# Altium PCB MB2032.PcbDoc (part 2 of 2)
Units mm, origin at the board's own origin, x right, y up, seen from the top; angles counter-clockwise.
Board outline 43.1 x 54.35 mm, 4 copper layers (Top Layer, Internal 1, Internal 2, Bottom Layer), stack 1.614 mm thick; 112 components, 86 nets, 372 pads, 581 vias.
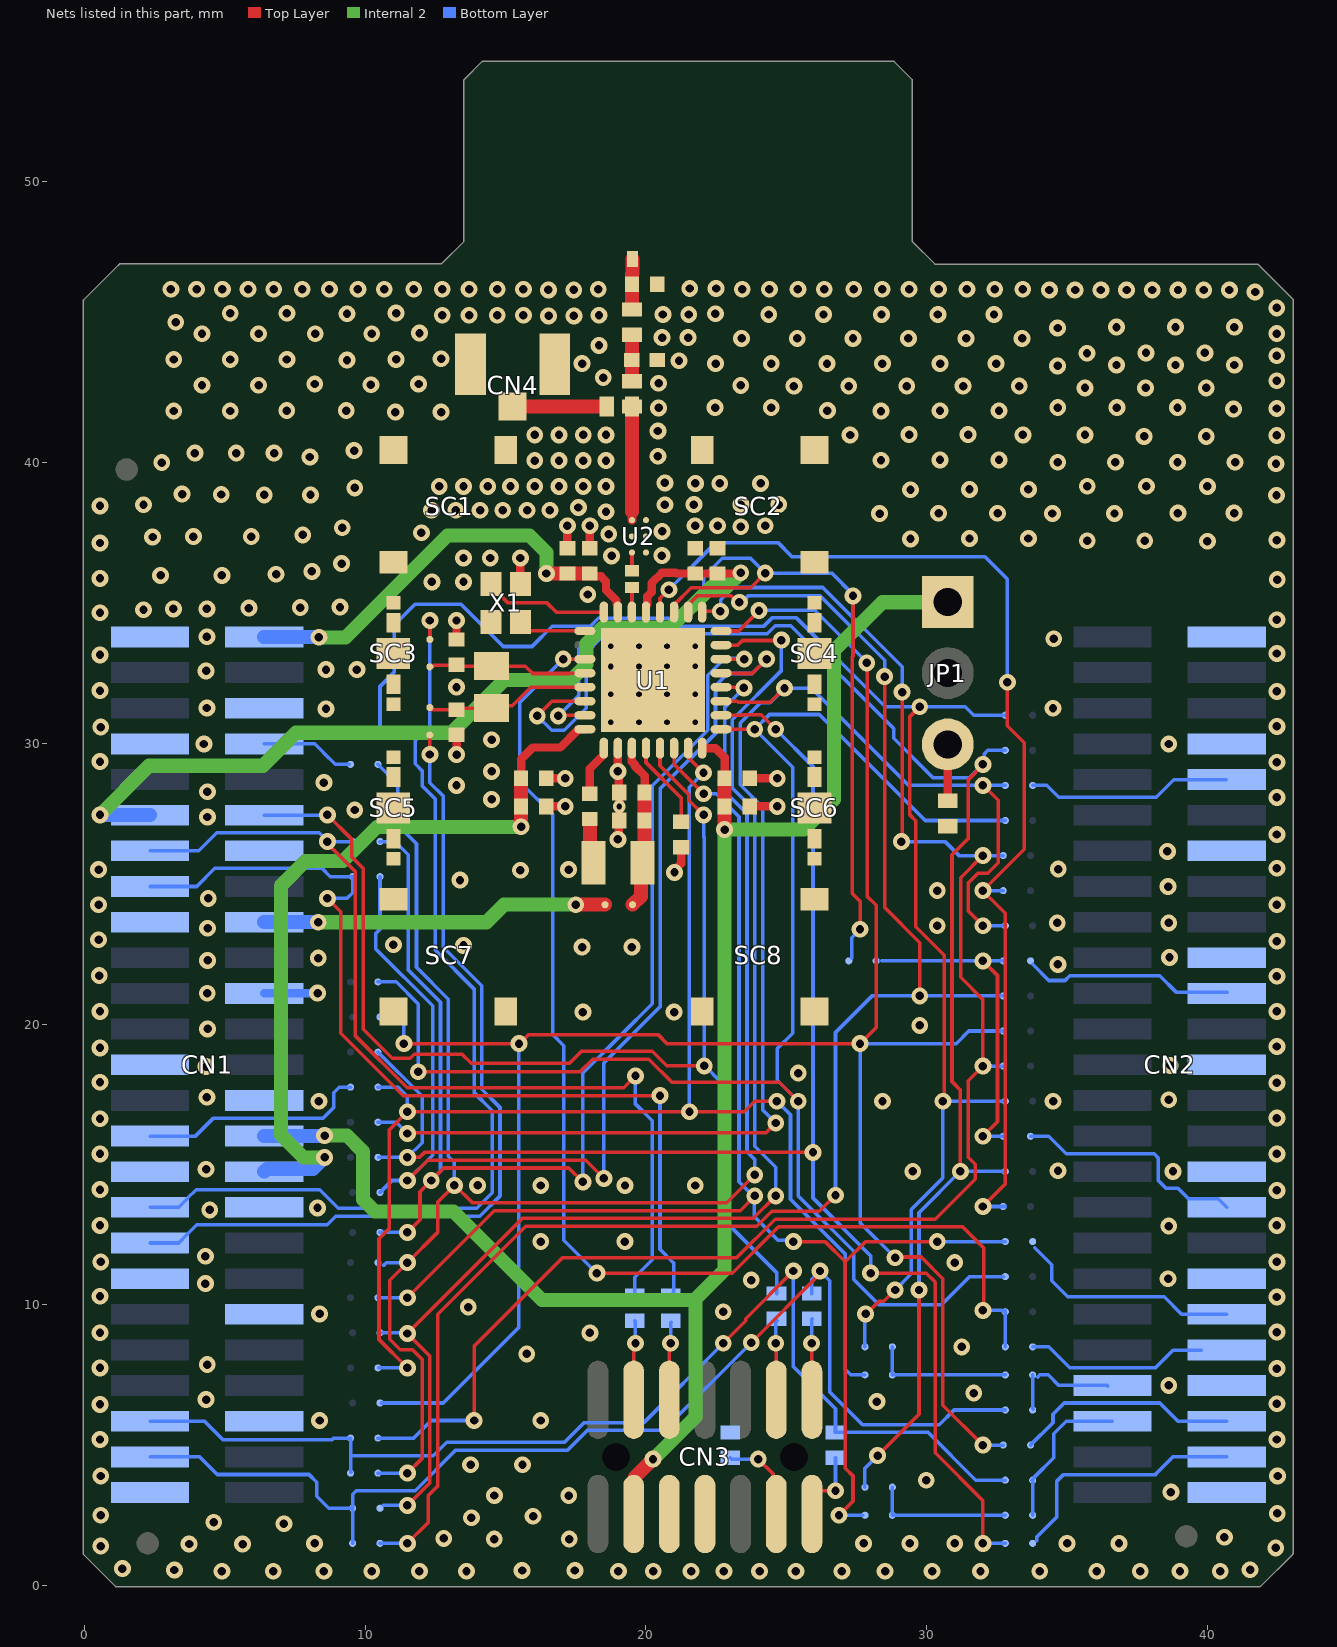
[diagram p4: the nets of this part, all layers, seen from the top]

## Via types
v1: diameter 0.6, hole 0.3, Top Layer to Bottom Layer, tented both sides, 564 vias
v2: diameter 0.45, hole 0.2, Top Layer to Bottom Layer, tented both sides, 17 vias

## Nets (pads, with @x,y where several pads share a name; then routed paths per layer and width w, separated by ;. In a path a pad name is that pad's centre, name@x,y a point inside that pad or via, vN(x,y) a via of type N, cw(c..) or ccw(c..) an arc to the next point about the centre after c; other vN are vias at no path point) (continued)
GND: C1.1 C2.1 C3.1 C4.1 C5.1 C6.1 C8.1 C9.2 C10.1 C11.1 C12.1 C13.1 C14.1 C15.1 C16.1 CN1.1 CN1.6 CN1.7 CN1.14 CN1.17 CN1.22 CN1.25 CN1.28 CN1.31 CN1.34 CN1.37 CN1.40 CN1.46 CN1.49 CN2.2 CN2.8 CN2.14 CN2.20 CN2.26 CN2.32 CN2.38 CN2.44 CN2.50 CN3.5 CN3.7 CN4.2 CN4.3 R3.1 R9.1 SC1.1 SC2.1 SC3.1 SC4.1 SC5.1 SC6.1 SC7.1 SC8.1 U1.26 U1.33 U2.A2 U2.B1 U2.B2 U2.B3 X1.2 X1.4 | length 13.1
  Top Layer w0.3: C9.2@13.25,30.3 13.251,30.299 13.251,29.597 v1(13.253,29.595) ; C8.1@13.25,33.7 v1(13.25,34.375) ; X1.2@15.525,35.925 v1(15.525,36.6) ; C14.1@16.45,27.75 v1(17.125,27.75) ; C11.1@16.45,28.75 v1(17.125,28.75) ; C3.1@17.2,36.95 v1(17.2,37.75) ; C4.1@18,36.95 v1(18,37.75) ; v1(19,26.575) 19.025,26.6 19.025,27.225 C15.1@19.05,27.25 C12.1@19.05,28.25 19.025,28.275 v1@19.025,28.925 ; v1(19,29) U1.26@19,29.825 ; v1(21.015,25.4) 21.015,25.48 21.25,25.714 C16.1@21.25,26.3 ; C13.1@23.7,27.75 v1(24.675,27.75) ; C10.1@23.7,28.75 v1(24.675,28.75)
  Bottom Layer w0.3: CN1.22@6.401,21.088 8.288,21.088 v1(8.3,21.1)
  other v1: 4.894,0.508 6.723,0.508 8.527,0.508 10.228,0.508 11.93,0.508 13.607,0.508 19.017,0.508 20.261,0.508 21.608,0.508 22.776,0.508 24.046,0.508 25.341,0.508 26.978,0.508 28.516,0.508 30.193,0.508 31.916,0.508 34.028,0.508 36.06,0.508 37.61,0.508 39.024,0.508 40.454,0.508 15.588,0.533 17.467,0.533 3.2,0.55 41.521,0.559 1.35,0.6 42.436,1.337 0.575,1.4 5.631,1.473 3.725,1.475 8.196,1.499 27.75,1.5 29.4,1.5 31,1.5 35,1.5 36.85,1.5 14.597,1.651 17.264,1.651 12.794,1.676 40.607,1.716 7.1,2.2 4.6,2.25 13.778,2.413 15.98,2.464 0.575,2.5 42.486,2.565 17.25,3.2 14.602,3.205 38.7,3.325 29.983,3.75 0.575,3.9 42.5,3.9 13.75,4.3 15.6,4.3 0.55,5.2 42.475,5.2 8.375,5.875 16.25,5.875 0.55,6.45 42.475,6.475 28.225,6.55 4.331,6.62 31.675,6.85 38.625,7.125 42.475,7.725 0.55,7.75 4.372,7.865 15.75,8.25 31.25,8.5 0.55,9 18.003,8.998 42.475,9.025 8.375,9.675 22.75,9.75 13.67,9.915 42.475,10.275 0.55,10.3 4.306,10.75 23.75,10.875 38.6,10.925 31,11.5 0.575,11.525 42.475,11.525 4.306,11.725 16.25,12.25 19.25,12.25 38.625,12.8 0.55,12.825 42.475,12.825 4.458,13.376 8.299,13.449 42.475,14.075 0.55,14.1 16.253,14.248 19.253,14.248 21.753,14.248 14,14.25 29.503,14.748 38.775,14.75 34.678,14.773 4.331,14.824 0.55,15.375 42.475,15.375 0.55,16.625 42.475,16.65 8.35,17.25 28.425,17.25 34.503,17.248 38.625,17.3 4.356,17.39 42.475,17.9 0.55,17.925 25.425,18.25 4.331,18.482 38.675,18.525 0.55,19.15 42.475,19.2 4.382,19.828 29.75,19.95 17.75,20.425 21,20.425 0.55,20.45 42.475,20.45 4.372,21.098 42.475,21.7 0.525,21.725 34.675,22.125 4.382,22.266 8.325,22.35 38.65,22.375 17.725,22.74 19.5,22.74 13.5,22.8 11,22.825 42.475,22.95 0.5,23 4.382,23.409 30.375,23.5 34.65,23.6 38.625,23.6 0.5,24.25 42.475,24.25 4.407,24.476 30.375,24.75 38.6,24.893 13.375,25.125 0.5,25.5 15.525,25.48 17.246,25.5 34.684,25.518 42.475,25.55 38.575,26.15 42.475,26.75 4.375,27.375 9.625,27.625 14.5,28 42.475,28.075 4.375,28.275 13.25,28.5 8.525,28.6 14.5,29 42.475,29.325 0.55,29.35 4.25,29.975 38.625,29.975 14.5,30.125 0.575,30.575 42.475,30.6 8.6,31.225 4.356,31.258 34.5,31.25 42.475,31.85 0.55,31.875 13.25,32 4.331,32.579 8.6,32.625 9.7,32.625 0.55,33.15 42.475,33.2 34.525,33.725 4.356,33.798 42.475,34.4 0.55,34.65 2.1,34.759 3.163,34.789 4.356,34.789 5.855,34.814 7.684,34.835 9.1,34.85 17.925,35.3 12.375,35.75 13.5,35.75 42.486,35.832 0.55,35.875 2.71,35.982 4.894,35.982 6.825,36.023 8.1,36.125 9.159,36.402 13.5,36.6 14.45,36.6 18.775,36.675 20.568,36.685 0.551,37.135 40,37.2 35.718,37.214 37.77,37.214 42.477,37.236 29.423,37.283 31.524,37.296 33.624,37.296 2.425,37.35 3.878,37.363 5.936,37.363 7.775,37.425 18.675,37.45 12,37.5 20.575,37.55 9.181,37.677 23.375,37.715 21.75,37.75 22.55,37.75 24.25,37.75 28.323,38.183 30.424,38.196 32.524,38.196 34.476,38.186 36.69,38.186 38.95,38.2 40.95,38.2 18.576,38.25 12.361,38.3 13.225,38.3 14.089,38.3 14.899,38.3 15.763,38.3 16.575,38.3 17.591,38.4 0.551,38.456 2.1,38.5 20.675,38.5 21.708,38.502 23.382,38.502 24.732,38.502 42.461,38.837 4.869,38.862 6.4,38.85 8.05,38.85 3.475,38.875 29.423,39.033 31.524,39.046 33.624,39.046 9.625,39.1 12.636,39.15 13.5,39.15 14.364,39.15 15.174,39.15 16.038,39.15 16.902,39.15 17.766,39.15 18.576,39.15 35.718,39.158 37.824,39.158 40,39.15 21.762,39.258 22.626,39.258 24.084,39.258 20.675,39.275 42.444,39.96 2.75,40 34.668,40.014 36.72,40.014 38.934,40.014 40.986,40.014 16.038,40.068 16.902,40.068 17.766,40.068 18.576,40.068 28.373,40.083 30.474,40.096 32.574,40.096 8.025,40.2 20.425,40.225 3.931,40.338 5.404,40.338 6.75,40.338 9.6,40.425 37.746,40.932 39.96,40.932 42.467,40.97 16.038,40.986 16.902,40.986 17.766,40.986 18.576,40.986 27.273,40.983 29.374,40.996 31.474,40.996 33.426,40.986 35.64,40.986 20.425,41.125 11.075,41.8 12.7,41.8 28.373,41.833 3.175,41.838 5.191,41.838 7.2,41.85 9.325,41.85 26.46,41.85 30.474,41.846 32.574,41.846 40.932,41.904 42.467,41.927 20.45,41.95 22.464,41.958 24.462,41.958 34.668,41.958 36.774,41.958 38.934,41.958 35.64,42.66 37.8,42.66 39.96,42.66 25.27,42.725 27.223,42.725 29.29,42.725 31.298,42.725 33.298,42.725 4.183,42.755 6.2,42.755 23.373,42.75 10.2,42.775 8.2,42.8 11.9,42.8 20.45,42.825 42.467,42.918 18.475,43.025 34.661,43.444 36.762,43.476 38.862,43.476 40.962,43.476 17.725,43.525 22.48,43.525 24.461,43.525 26.448,43.525 28.423,43.525 30.48,43.525 32.473,43.525 21.175,43.625 9.35,43.65 3.175,43.671 5.191,43.671 7.208,43.671 11.1,43.675 12.7,43.7 42.467,43.807 35.711,43.897 37.812,43.909 39.912,43.909 18.325,44.175 23.405,44.425 25.386,44.425 27.373,44.425 29.348,44.425 31.405,44.425 33.398,44.425 20.575,44.45 21.5,44.45 4.183,44.588 6.2,44.588 8.216,44.588 10.232,44.588 42.467,44.594 11.932,44.613 34.661,44.794 36.762,44.826 38.862,44.826 40.962,44.826 3.25,45 16.531,45.224 17.431,45.224 12.742,45.25 13.7,45.25 14.7,45.25 15.631,45.25 18.325,45.249 20.6,45.275 21.525,45.275 24.37,45.275 26.323,45.275 28.39,45.275 30.398,45.275 32.398,45.275 9.35,45.3 22.473,45.3 5.191,45.321 7.208,45.321 11.1,45.325 42.467,45.509 41.699,46.077 16.525,46.15 17.425,46.15 34.372,46.147 35.288,46.147 36.204,46.147 37.12,46.147 38.036,46.147 38.952,46.147 39.868,46.147 40.784,46.147 3.077,46.177 3.992,46.177 4.908,46.177 5.824,46.177 6.74,46.177 7.757,46.175 8.722,46.175 9.738,46.175 10.675,46.175 11.725,46.175 12.742,46.175 13.7,46.175 14.7,46.175 15.631,46.175 18.3,46.175 23.43,46.175 24.395,46.175 25.411,46.175 26.348,46.175 27.398,46.175 28.415,46.175 29.373,46.175 30.423,46.175 31.43,46.175 32.423,46.175 33.423,46.175 21.561,46.2 22.498,46.2
  other v2: 19.05,27.75 18.75,30.75 19.75,30.75 20.75,30.75 21.75,30.75 18.75,31.75 19.75,31.75 20.75,31.75 21.75,31.75 18.75,32.737 19.75,32.737 20.75,32.75 21.75,32.75 18.75,33.457 19.75,33.457 20.75,33.457 21.75,33.457
LD1: CN2.10 SB9.2 | length 7.3
  Bottom Layer w0.127: SB9.2@33.775,28.5 34.275,28.5 34.7,28.075 38.175,28.075 38.8,28.7 CN2.10@40.675,28.7
LD2: CN1.29 SB16.2 | length 8.2
  Bottom Layer w0.127: CN1.29@2.334,16.008 3.953,16.008 4.595,16.65 8.5,16.65 8.875,17.025 8.875,17.55 9.075,17.75 SB16.2@9.475,17.75
LD3: CN2.48 SB7.2 | length 8.8
  Bottom Layer w0.127: 33.925,1.6 33.925,1.725 34.625,2.425 34.625,3.7 34.875,3.95 38.15,3.95 ; 38.138,3.953 38.764,4.578 CN2.48@40.688,4.578
LPUART_CTS: SB49.1 SB52.2 SB53.2 | length 11.7
  Top Layer w0.127: v1(32,16) 32.523,16.523 32.523,21.727 v1(32,22.25)
  Bottom Layer w0.127: 28.4,22.25 v1(32,22.25) SB52.2@32.7,22.25 ; v1(32,16) SB53.2@32.725,16 SB53.2@32.75,16
LPUART_RTS: CN1.8 SB45.2 | length 3.3
  Bottom Layer w0.127: CN1.8@6.401,29.978 8.203,29.978 8.5,29.682 8.5,29.675 8.925,29.25 SB45.2@9.425,29.25
LPUART_RX: SB31.2 SB35.2 SB57.1 | length 5
  Bottom Layer w0.127: SB31.2@28.775,2.5 SB57.1@32.8,2.5 ; SB35.2@28.775,3.5 28.775,2.55 SB31.2@28.8,2.525
LPUART_TX: SB29.2 SB33.2 SB55.1 | length 5
  Bottom Layer w0.127: SB29.2@28.775,7.5 SB33.2@28.775,8.5 ; SB29.2@28.8,7.525 28.825,7.5 SB55.1@32.8,7.5
NetANT1_1: ANT1.1 C1.2 R10.2 | length 1.7
  Top Layer w0.5: R10.2@19.5,45.5 C1.2@19.5,46.35 ; C1.2@19.5,46.425 19.5,46.725 19.52,46.745 ANT1.1@19.52,47.25
NetC2_2: C2.2 R1.2 R10.1 | length 1.6
  Top Layer w0.5: R1.2@19.5,42.9 R10.1@19.5,44.525
NetC7_1: C7.1 U1.14 | length 0.9
  Top Layer w0.15: U1.14@19.5,34.675 C7.1@19.5,35.55
NetC7_2: C7.2 U2.A3 | length 0.6
  Top Layer w0.15: C7.2@19.5,36.15 U2.A3@19.5,36.795
NetC8_2: C8.2 SB1.2 U1.20 X2.2 | length 5.6
  Top Layer w0.127: SB1.2@12.301,32.749 12.412,32.749 12.438,32.775 13.225,32.775 C8.2@13.25,32.8 ; C8.2@13.3,32.775 13.325,32.75 X2.2@14.5,32.75 15.7,32.75 15.963,32.487 17.263,32.487 17.276,32.5 U1.20@17.825,32.5
NetC9_1: C9.1 SB2.2 U1.21 X2.1 | length 5.7
  Top Layer w0.127: SB2.2@12.301,31.201 12.414,31.201 ; 12.415,31.2 C9.1@13.25,31.2 ; C9.1@13.325,31.25 X2.1@14.5,31.25 14.591,31.341 15.241,31.341 15.9,32 U1.21@17.8,32
NetC12_2: C12.2 C15.2 L3.1 SB3.1 U1.27 | length 5.9
  Top Layer w0.3: U1.27@19.5,29.825 19.5,29.349 19.6,29.249 19.6,29.2 19.95,28.85 C12.2@19.95,28.3
  Top Layer w0.5: SB3.1@19.525,24.25 19.82,24.545 19.82,25.695 L3.1@19.875,25.75 ; L3.1@19.875,25.775 19.95,25.85 C15.2@19.95,27.25 C12.2@19.95,28.25
NetC16_2: C16.2 U1.28 | length 3.1
  Top Layer w0.127: U1.28@20,29.825 20,29.314 21.25,28.064 C16.2@21.25,27.2
NetCN2_22: CN2.22 SB52.1 | length 7.5
  Bottom Layer w0.127: 33.775,22.125 34.35,21.55 34.925,21.55 35.1,21.725 38.3,21.725 38.9,21.125 CN2.22@40.7,21.125
NetCN2_34: CN2.34 SB53.1 | length 8.5
  Bottom Layer w0.127: SB53.1@33.7,16 34.35,16 34.975,15.375 38.1,15.375 38.25,15.225 38.25,14.425 38.525,14.15 38.95,14.15 39.325,13.775 40.385,13.775 CN2.34@40.691,13.468
NetCN2_43: CN2.43 SB54.2 SB55.2 | length 3.9
  Bottom Layer w0.127: SB55.2@33.775,7.5 33.775,6.3 SB54.2@33.8,6.275 ; 33.95,7.425 34.025,7.5 34.325,7.5 34.7,7.125 36.425,7.125 CN2.43@36.45,7.1
NetCN2_45: CN2.45 SB56.2 SB57.2 | length 5.5
  Bottom Layer w0.127: SB56.2@33.75,3.75 33.775,3.725 SB57.2@33.775,2.5 ; SB56.2@33.775,3.75 33.775,3.784 33.838,3.848 33.838,3.864 34.525,4.55 34.525,5.4 34.975,5.85 CN2.45@36.6,5.85
NetCN3_4: CN3.4 R7.1 | length 2.8
  Top Layer w0.127: CN3.4@19.561,6.614 19.561,8.561 v1(19.625,8.625)
  Bottom Layer w0.127: R7.1@19.6,9.425 19.625,9.4 v1(19.625,8.625)
NetCN3_6: CN3.6 R6.1 | length 2.8
  Top Layer w0.127: CN3.6@20.831,6.614 20.831,8.581 v1(20.875,8.625)
  Bottom Layer w0.127: v1(20.875,8.625) 20.875,9.35 R6.1@20.9,9.375
NetCN3_11: CN3.11 R9.2 | length 3.2
  Top Layer w0.127: v1(24,4.5) 24.524,3.976 24.524,2.662 CN3.11@24.641,2.544
  Bottom Layer w0.127: R9.2@23,4.55 23.05,4.5 v1(24,4.5)
NetCN3_12: CN3.12 R5.1 | length 2.8
  Top Layer w0.127: v1(24.625,8.625) 24.641,8.609 CN3.12@24.641,6.614
  Bottom Layer w0.127: v1(24.625,8.625) 24.625,9.375 R5.1@24.675,9.425
NetCN3_13: CN3.13 R8.2 | length 2.7
  Top Layer w0.127: CN3.13@25.911,2.544 25.911,3.092 26.195,3.375 v1(26.75,3.375)
  Bottom Layer w0.127: v1(26.75,3.375) R8.2@26.75,4.55
NetCN3_14: CN3.14 R4.1 | length 2.9
  Top Layer w0.127: v1(25.9,8.625) 25.911,8.614 CN3.14@25.911,6.614
  Bottom Layer w0.127: v1(25.9,8.625) 25.9,9.475 R4.1@25.925,9.5
NetCN4_1: CN4.1 R2.2 | length 3.4
  Top Layer w0.5: CN4.1@15.25,42 R2.2@18.6,42
NetJP1_3: JP1.3 R3.2 | length 2
  Top Layer w0.3: R3.2@30.75,27.95 JP1.3@30.75,29.96 JP1.3@30.75,29.975
NetL2_1: L2.1 L3.2 | length 1.6
  Top Layer w0.5: L2.1@18,27.3 18,25.925 L3.2@18.125,25.8
NetL2_2: L2.2 U1.25 | length 1.8
  Top Layer w0.3: L2.2@18,28.225 18,29.1 18.5,29.6 U1.25@18.5,29.825
NetR1_1: R1.1 R2.1 U2.A1 | length 4.1
  Top Layer w0.32: U2.A1@19.5,37.949 19.5,38.25
  Top Layer w0.5: 19.5,38.25 R2.1@19.5,42
NetU1_16: U1.16 X1.3 | length 4.2
  Top Layer w0.127: X1.3@14.65,35.45 14.787,35.314 14.787,35.299 15.086,35 16.475,35 16.8,34.675 U1.16@18.475,34.675
NetU1_17: U1.17 X1.1 | length 2.4
  Top Layer w0.127: X1.1@15.525,34.325 15.837,34.013 17.812,34.013 U1.17@17.825,34
OSC32_IN: CN1.33 SB1.1 | length 35.4
  Top Layer w0.127: SB1.1@12.3,33.7 v1(12.3,34.375)
  Bottom Layer w0.127: CN1.33@2.334,13.468 3.356,13.468 3.663,13.775 3.663,13.788 3.975,14.1 8.375,14.1 9.039,13.437 13.97,13.437 14.523,13.99 14.523,16.91 13.875,17.558 13.875,21.25 12.5,22.625 12.5,28.008 12.023,28.485 12.023,29.027 11.775,29.275 11.775,30.1 12.3,30.625 v1(12.3,34.375)
OSC32_OUT: CN1.35 SB2.1 | length 30.6
  Top Layer w0.127: v1(12.3,29.6) SB2.1@12.3,30.3
  Bottom Layer w0.127: CN1.35@2.334,12.198 3.356,12.198 3.663,12.505 3.663,12.513 4,12.85 8.65,12.85 8.95,13.15 14.075,13.15 14.8,13.875 14.8,17.025 14.152,17.673 14.152,21.365 12.777,22.74 12.777,28.123 12.3,28.6 v1(12.3,29.6)
PA0: SB4.2 SB6.2 SB12.2 SB23.2 U1.8 | length 77.2
  Top Layer w0.127: v1(11.375,19.3) 15.5,19.3 15.825,19.625 20.425,19.625 20.748,19.302 21.34,19.302 21.342,19.3 v1(27.625,19.3) 28.2,19.875 28.2,24.225 27.875,24.55 27.875,32.857 v1(27.866,32.866) ; U1.8@22.675,34 23.3,34 v1(24.024,34.726) ; v1(28.875,11.675) 28.9,11.7 29.8,11.7 30.577,10.923 30.577,6.423 v1(32,5)
  Bottom Layer w0.127: SB4.2@10.526,20.274 SB4.2@10.639,20.274 ; SB23.2@10.575,6.5 12.775,6.5 15.475,9.2 v1(15.475,19.3) ; SB4.2@10.64,20.275 11.075,20.275 11.375,19.975 v1(11.375,19.3) ; v1(24.024,34.726) 24.041,34.742 26.007,34.742 27.866,32.884 v1(27.866,32.866) ; v1(28.875,11.675) 27.625,12.925 v1(27.625,19.3) 31.05,19.3 31.5,19.75 SB12.2@32.725,19.75 ; v1(32,5) SB6.2@32.725,5
PA1: SB25.2 SB38.2 U1.7 | length 47.2
  Top Layer w0.127: v1(11.5,2.85) 12.298,3.648 12.298,4.465 12.3,4.467 12.3,8.175 v1(11.5,8.975) 15.6,13.075 23.825,13.075 v1(24.625,13.875) ; U1.7@22.675,33.5 23.274,33.5 23.435,33.661 24.811,33.661 v1(24.825,33.675)
  Bottom Layer w0.127: SB25.2@10.525,9 11.475,9 v1(11.5,8.975) ; 10.65,2.85 v1(11.5,2.85) ; v1(24.625,13.875) 24.625,14.9 23.875,15.65 23.875,27.608 23.075,28.408 23.075,30.835 24.812,32.573 24.812,32.887 24.813,32.888 24.813,33.663 v1(24.825,33.675)
PA2: SB11.2 SB19.2 U1.6 | length 44.6
  Top Layer w0.127: v1(11.5,12.575) 11.95,13.025 11.95,14.025 12.796,14.871 17.254,14.871 v1(17.75,14.375) ; U1.6@22.675,33 v1(23.5,33)
  Bottom Layer w0.127: SB19.2@10.525,12.575 v1(11.5,12.575) ; SB11.2@10.525,26.5 11.05,26.5 11.525,26.025 11.525,21.925 12.679,20.771 12.679,14.754 v1(12.35,14.425) ; v1(17.75,14.375) 17.75,18.25 19.125,19.625 20.225,20.725 20.225,28.492 22.198,30.465 22.198,32.423 22.8,33.025 23.2,33.025 ; 23.2,33 v1(23.5,33)
PA3: SB17.2 SB30.2 U1.5 | length 44.1
  Top Layer w0.127: v1(11.5,14.425) 12.223,15.148 17.852,15.148 v1(18.5,14.5) ; U1.5@22.675,32.5 23.274,32.5 23.287,32.487 23.787,32.487 24.299,32.999 v1(24.299,33)
  Bottom Layer w0.127: SB30.2@10.525,14 10.95,14.425 v1(11.5,14.425) 12.4,15.325 12.4,15.808 12.402,15.81 12.402,20.225 ; SB17.2@10.525,25.25 10.525,23.375 10.375,23.225 10.375,22.675 12.4,20.65 12.4,20.225 ; v1(18.5,14.5) 18.5,18.608 20.502,20.61 20.502,28.377 22.475,30.35 22.475,32.05 22.912,32.487 23.787,32.487 24.299,32.999 v1(24.299,33)
PA8: SB39.2 SB41.2 SB51.1 U1.9 | length 58.8
  Top Layer w0.127: v1(13.875,5.875) 13.875,8.525 17.025,11.675 23.225,11.675 24.6,13.05 30.3,13.05 31.725,14.475 31.725,15 31.475,15.25 31.475,17.975 v1(32,18.5) 32,20.875 31.21,21.665 31.21,25.209 v1(32,26) ; U1.9@22,34.675 22.025,34.7 v1(22.65,34.7) ; v1(29.1,26.5) 29.125,26.525 v1(29.125,31.825)
  Bottom Layer w0.127: SB51.1@10.45,5.25 11.725,5.25 12.35,5.875 v1(13.875,5.875) ; v1(22.65,34.7) 22.666,34.716 22.666,35.116 23.1,35.55 26.3,35.55 29.125,32.725 v1(29.125,31.825) ; v1(29.1,26.5) 30.65,26.5 31.15,26 v1(32,26) SB41.2@32.725,26 ; v1(32,18.5) SB39.2@32.725,18.5
PA9: SB46.2 SB47.2 U1.10 | length 58.8
  Top Layer w0.127: v1(11.5,1.5) 12.25,2.25 12.25,3.208 12.575,3.533 12.575,4.35 12.577,4.352 12.577,9.66 15.715,12.798 23.948,12.798 24.45,13.3 24.458,13.3 24.485,13.327 26.177,13.327 v1(26.75,13.9) ; U1.10@21.5,34.675 21.5,34.925 21.839,35.264 23.015,35.264 23.253,35.026 v1(23.326,35.026) ; v1(28.5,32.375) 28.5,24.15 29.75,22.9 v1(29.75,21)
  Bottom Layer w0.127: SB46.2@10.525,1.5 v1(11.5,1.5) ; v1(23.326,35.026) 23.412,35.026 23.637,35.25 26.208,35.25 28.5,32.958 v1(28.5,32.375) ; v1(26.75,13.9) 26.75,19.7 28.05,21 v1(29.75,21) SB47.2@32.725,21
PA10: SB48.2 SB49.2 U1.11 | length 40.5
  Top Layer w0.127: U1.11@21,34.675 21,34.925 21.615,35.541 23.727,35.541 v1(24.25,36.063) ; v1(27.375,35.25) 27.375,33.101 27.348,33.074 27.348,24.652 27.625,24.375 v1@27.625,23.425
  Bottom Layer w0.127: SB48.2@10.525,30.5 10.525,32.025 11.025,32.525 11.025,34.2 11.773,34.948 13.41,34.948 14.91,33.448 15.94,33.448 16.665,34.173 18.023,34.173 18.304,34.454 21.271,34.454 22.05,35.233 22.05,35.921 22.717,36.588 23.725,36.588 v1(24.25,36.063) 26.612,36.063 27.375,35.3 v1(27.375,35.25) ; 27.325,22.35 27.325,23.075 v1(27.625,23.375)
PA11: SB43.2 SB44.2 U1.12 | length 39.6
  Top Layer w0.127: U1.12@20.5,34.675 20.5,35.172 20.799,35.471 v1(20.816,35.471) ; v1(32,13.5) 32.8,14.3 32.8,23.95 v1(32,24.75) 33.475,26.225 33.475,30.025 32.875,30.625 v1(32.875,32.175)
  Bottom Layer w0.127: v1(20.816,35.471) 22.495,37.15 24.7,37.15 25.198,36.652 26.14,36.652 26.142,36.65 32.075,36.65 32.875,35.85 v1(32.875,32.175) ; v1(32,13.5) SB44.2@32.725,13.5 SB44.2@32.8,13.5 ; v1(32,24.75) SB43.2@32.725,24.75
PB0: SB8.1 SB28.1 SB45.1 U1.4 | length 60.5
  Top Layer w0.127: v1(11.5,4) 12.023,4.523 12.023,8.06 11.683,8.4 11.25,8.4 10.875,8.775 10.875,10.875 v1(11.5,11.5) 12.575,12.575 12.575,13.65 v1(13.175,14.25) ; v1@13.175,14.275 13.825,13.625 15.367,13.625 15.371,13.629 22.879,13.629 v1(23.875,14.625) ; U1.4@22.675,32 23.46,32 v1(23.487,31.973)
  Bottom Layer w0.127: SB28.1@10.45,4 v1(11.5,4) ; SB45.1@10.45,29.25 11.15,28.55 11.15,27.1 11.825,26.425 11.825,22.017 12.956,20.886 12.956,15.294 13.175,15.075 v1(13.175,14.25) ; 10.65,11.4 10.75,11.5 v1(11.5,11.5) ; v1(23.487,31.973) 23.487,31.96 22.798,31.271 22.798,28.294 23.598,27.494 23.598,15.452 23.875,15.175 v1(23.875,14.625)
PB1: SB9.1 SB10.1 SB22.1 U1.3 | length 50
  Top Layer w0.127: v1(11.5,16.1) 11.525,16.125 24.275,16.125 v1(24.625,16.475) ; U1.3@22.675,31.5 23.247,31.5 23.287,31.46 24.425,31.46 v1(24.933,31.967) ; v1@31.975,23.525 31.487,24.014 31.487,25.037 31.825,25.375 32.175,25.375 32.55,25.75 32.55,27.975 v1@32,28.525
  Bottom Layer w0.127: SB10.1@10.45,16.5 11.1,16.5 v1(11.5,16.1) ; v1(24.625,16.475) 24.152,16.948 24.152,27.723 23.352,28.523 23.352,30.721 24.081,31.45 24.416,31.45 v1(24.933,31.967) 25.883,31.967 29.35,28.5 v1(32,28.5) SB9.1@32.8,28.5 ; v1(32,23.5) 32.75,23.5 SB22.1@32.775,23.525
PB2: SB5.1 SB7.1 SB13.1 U1.2 | length 56.4
  Top Layer w0.127: v1(11.5,15.25) 11.933,15.25 12.108,15.425 v1(25.95,15.425) ; U1.2@22.675,31 23.424,31 23.437,31.013 24.112,31.013 v1(24.625,30.5) ; v1(28,11.125) 29.983,11.125 30.3,10.808 30.3,4.725 32,3.025 v1(32,1.5)
  Bottom Layer w0.127: SB13.1@10.45,19 12.025,17.425 12.025,15.775 v1(11.5,15.25) SB5.1@10.475,15.25 ; v1(24.625,30.5) 25.95,29.175 25.95,13.8 28,11.75 v1(28,11.125) ; v1(32,1.5) SB7.1@32.8,1.5
PB3: SB14.1 SB15.1 SB24.1 U1.1 | length 58.1
  Top Layer w0.127: v1(11.889,18.3) 17.65,18.3 18.098,18.748 20.102,18.748 20.925,17.925 24.75,17.925 v1(25.425,17.25) ; U1.1@22.675,30.5 v1(23.875,30.5)
  Bottom Layer w0.127: SB15.1@10.45,21.5 11.1,21.5 11.889,20.712 v1(11.889,18.3) ; SB24.1@32.75,11 31.525,11 30.525,10 28.3,10 27.4,10.9 27.4,11.9 25.425,13.875 v1(25.425,17.25) 24.675,18 24.675,19.125 25.225,19.675 25.225,29.15 v1(23.875,30.5) 24.4,31.025 26.175,31.025 29.95,27.25 SB14.1@32.8,27.25
PB4: SB16.1 SB18.1 SB29.1 U1.31 | length 50.8
  Top Layer w0.127: v1(11.5,7.75) 10.49,8.76 10.49,12.354 10.85,12.715 10.85,16.225 v1(11.5,16.875) v1(21.55,16.875) 23.5,16.875 23.875,17.25 v1(24.665,17.25) ; U1.31@21.5,29.825 21.533,29.792 21.533,29.467 v1(22.05,28.95)
  Bottom Layer w0.127: SB16.1@10.45,17.75 11.175,17.75 11.5,17.425 v1(11.5,16.875) ; SB18.1@10.475,7.75 v1(11.5,7.75) ; v1(21.55,16.875) 21.538,16.887 21.538,28.439 v1(22.05,28.95) ; v1(24.665,17.25) 25.148,16.767 25.148,13.76 27.102,11.806 27.102,7.698 27.3,7.5 SB29.1@27.8,7.5
PB5: SB20.1 SB21.1 SB31.1 U1.30 | length 53.2
  Top Layer w0.127: v1(11.5,10.25) 14.598,13.348 15.481,13.348 15.485,13.352 23.352,13.352 v1(23.875,13.875) ; U1.30@21,29.825 21,29.25 22.05,28.2 v1(22.052,28.2) ; v1(25.25,12.25) 26.375,12.25 27.1,11.525 ; v1(26.875,2.5) 27.375,3 27.375,3.9 27.1,4.175 27.1,11.525 ; v1(30.375,12.25) 27.825,12.25 27.1,11.525
  Bottom Layer w0.127: SB21.1@10.45,10.25 v1(11.5,10.25) ; v1(22.052,28.2) 22.5,28.2 23.313,27.386 23.313,14.387 23.85,13.85 23.85,13.15 24.7,12.3 25.2,12.3 v1(25.25,12.25) ; v1(26.875,2.5) SB31.1@27.725,2.5 ; v1(30.375,12.25) SB20.1@32.8,12.25
PB6: SB32.1 SB33.1 SB40.1 U1.23 | length 47.7
  Top Layer w0.127: v1(16.875,30.975) 16.9,31 U1.23@17.825,31 ; v1@27.85,9.675 28.3,10.125 28.475,10.125 v1(28.875,10.525) ; v1(29.75,31.3) 29.402,30.952 29.402,27.448 29.613,27.237 29.613,23.462 30.623,22.452 30.623,17.298 v1(30.575,17.25)
  Bottom Layer w0.127: v1(16.875,30.975) 17.6,31.7 17.6,33.35 18.427,34.177 24.202,34.177 24.49,34.465 25.36,34.465 28.525,31.3 v1(29.75,31.3) 31.375,31.3 31.675,31 SB32.1@32.8,31 ; SB33.1@27.8,8.5 27.8,9.65 v1(27.825,9.675) ; v1(28.875,10.525) 29.448,11.098 29.448,13.39 30.575,14.517 v1(30.575,17.25) SB40.1@32.8,17.25
PB7: SB34.1 SB35.1 SB42.1 U1.22 | length 53.9
  Top Layer w0.127: v1(16.125,30.975) 16.65,31.5 U1.22@17.825,31.5 ; v1(28.25,4.625) 29.725,6.1 v1(29.725,10.525) ; v1(31.2,14.75) 31.198,14.752 31.198,17.652 30.9,17.95 30.9,26.025 31.487,26.612 31.487,28.713 32,29.226 v1(32,29.25)
  Bottom Layer w0.127: v1(16.125,30.975) 16.638,30.462 17.088,30.462 17.877,31.251 17.877,33.235 18.542,33.9 24.317,33.9 24.605,34.188 25.162,34.188 28.825,30.525 28.825,30.175 30.223,28.777 31.527,28.777 v1(32,29.25) 32.057,29.307 32.057,29.632 32.175,29.75 SB34.1@32.8,29.75 ; SB35.1@27.8,3.5 27.8,4.175 v1(28.25,4.625) v1@28.275,4.65 ; v1(29.725,10.525) 29.725,13.275 v1(31.2,14.75) SB42.1@32.8,14.75
PB14: SB36.1 SB37.1 U1.19 | length 43.6
  Top Layer w0.127: v1(17.05,33) U1.19@17.825,33 ; v1(18.25,11.125) 23.075,11.125 24.723,12.773 31.277,12.773 32.025,12.025 v1@32.025,9.8
  Bottom Layer w0.127: v1(17.05,33) 15.502,31.452 15.502,28.636 16.675,27.463 16.675,19.625 17.075,19.225 17.075,12.3 v1(18.25,11.125) ; v1(32,9.8) 32.662,9.8 32.688,9.774 32.774,9.774 SB36.1@32.788,9.788 ; SB36.1@32.775,9.8 SB36.1@32.787,9.788 ; SB37.1@32.8,8.5 SB36.1@32.8,9.75 32.8,9.775 SB36.1@32.788,9.788 ; SB36.1@32.8,9.8 SB36.1@32.788,9.788
T_NRST: CN1.12 R5.2 U1.29 | length 44.7
  Top Layer w0.127: v1(8.65,27.45) 9.525,26.575 9.525,25.942 9.927,25.54 9.927,19.815 10.967,18.775 11.6,18.775 11.75,18.925 13.448,18.925 13.775,18.598 17.275,18.598 17.702,19.025 20.225,19.025 20.74,18.51 v1(22.075,18.51) ; U1.29@20.5,29.825 20.5,29.206 21.527,28.179 21.527,27.973 22.05,27.45 v1(22.052,27.45)
  Bottom Layer w0.127: CN1.12@6.401,27.438 8.638,27.438 v1(8.65,27.45) ; v1(22.052,27.45) 22.05,27.448 22.05,26.675 22.075,26.65 22.075,18.525 22.675,17.925 22.675,13.125 24.651,11.149 R5.2@24.651,10.397
T_SWCLK: CN1.15 R6.2 SB17.1 | length 33.8
  Top Layer w0.127: v1(8.65,24.475) 9.125,24 9.125,19.675 11.35,17.45 v1(20.5,17.45)
  Bottom Layer w0.127: CN1.15@2.334,24.898 3.991,24.898 4.636,25.543 8.457,25.543 8.75,25.25 SB17.1@9.55,25.25 ; v1(8.65,24.475) 9.35,24.475 9.55,24.675 SB17.1@9.55,25.25 ; SB17.1@9.575,25.25 SB17.1@9.55,25.25 ; v1(20.5,17.45) 20.5,11.975 20.975,11.5 ; R6.2@20.887,10.328 20.982,10.423 20.982,11.5
T_SWDIO: CN1.13 R7.2 SB11.1 | length 34
  Top Layer w0.127: v1@8.625,26.45 9.65,25.425 9.65,19.575 11.498,17.727 19.202,17.727 v1(19.625,18.15)
  Bottom Layer w0.127: CN1.13@2.334,26.168 4.067,26.168 4.712,26.813 8.362,26.813 v1@8.675,26.5 ; v1(8.65,26.5) v1@8.675,26.5 ; SB11.1@9.475,26.5 v1@8.675,26.5 ; R7.2@19.6,10.45 19.6,10.975 20.225,11.6 20.225,11.858 20.223,11.86 20.223,16.552 19.625,17.15 v1(19.625,18.15)
T_VCP_RX: CN1.45 R8.1 SB28.2 SB51.2 SB56.1 | length 40.3
  Top Layer w0.127: v1(22.75,8.625) 23.55,9.425 23.55,9.5 v1(25.25,11.2)
  Bottom Layer w0.127: CN1.45@2.334,5.848 4.274,5.848 4.925,5.198 8.823,5.198 8.875,5.25 SB51.2@9.475,5.25 9.475,4.625 ; SB28.2@9.5,4.025 9.475,4.05 9.475,4.625 ; v1(22.75,8.625) 19.927,5.802 17.802,5.802 17.1,5.1 12.9,5.1 12.425,4.625 9.475,4.625 ; v1(25.25,11.2) 25.25,7.8 26.75,6.3 R8.1@26.75,5.5 ; R8.1@26.725,5.475 26.749,5.45 30.05,5.45 31.75,3.75 SB56.1@32.8,3.75
T_VCP_TX: CN1.47 R4.2 SB38.1 SB46.1 SB54.1 | length 42.3
  Top Layer w0.127: v1(23.75,8.65) 26.2,11.1 v1(26.2,11.2)
  Bottom Layer w0.127: CN1.47@2.334,4.578 4.102,4.578 4.728,3.953 7.997,3.953 8.275,3.675 8.275,3.175 8.7,2.75 SB38.1@9.55,2.75 9.55,3.25 9.675,3.375 11.775,3.375 13.223,4.823 17.215,4.823 17.917,5.525 20.625,5.525 v1(23.75,8.65) ; SB46.1@9.55,1.5 SB38.1@9.55,2.725 ; R4.2@25.909,10.397 25.909,10.902 26.175,11.168 v1@26.175,11.225 ; v1(26.2,11.2) 26.55,10.85 26.55,6.892 27.715,5.727 30.452,5.727 30.975,6.25 SB54.1@32.8,6.25
USER1: CN2.46 SB6.1 | length 8.1
  Bottom Layer w0.127: SB6.1@33.7,5 34.5,5.8 34.5,6.1 34.9,6.5 38.3,6.5 38.952,5.848 CN2.46@40.691,5.848
USER2: CN2.40 SB20.2 | length 8.2
  Bottom Layer w0.127: 33.85,12.025 34.45,11.425 34.45,10.85 35.022,10.278 38.46,10.278 39.08,9.658 CN2.40@40.688,9.658
USER3: CN2.42 SB37.2 | length 6.6
  Bottom Layer w0.127: SB37.2@33.775,8.5 34.35,8.5 35.1,7.75 38.15,7.75 38.775,8.375 CN2.42@39.775,8.375
VDD1: C3.2 C4.2 CN1.2 U1.15 | length 16
  Top Layer w0.3: C4.2@18,36.05 18.105,35.945 18.399,35.945 18.575,35.769 18.575,35.461 18.95,35.086 18.95,34.95 19,34.9 U1.15@19,34.675
  Top Layer w0.5: v1(16.45,36.05) C3.2@17.2,36.05 C4.2@18,36.05
  Internal 2 w0.5: v1@8.375,33.775 9.3,33.775 12.925,37.4 15.85,37.4 16.45,36.8 v1(16.45,36.05)
  Bottom Layer w0.5: CN1.2@6.398,33.788 CN1.2@6.401,33.788 8.337,33.788 v1(8.35,33.775)
VDD2: C5.2 C6.2 CN1.11 U1.13 | length 33.1
  Top Layer w0.3: U1.13@20,34.675 20,34.9 20.05,34.95 20.05,35.236 20.2,35.386 20.2,35.703 20.568,36.071 21.063,36.071 21.085,36.05 C5.2@21.75,36.05 22.525,36.05 23.35,36.05 v1(23.375,36.075)
  Internal 2 w0.5: v1(0.55,27.45) 2.3,29.2 6.35,29.2 7.525,30.375 13.075,30.375 14.95,32.25 17.325,32.25 17.875,32.8 17.875,33.55 18.45,34.125 20.875,34.125 22.325,35.575 22.875,35.575 v1(23.375,36.075)
  Bottom Layer w0.5: v1(0.55,27.45) 0.556,27.444 2.326,27.444 CN1.11@2.331,27.438
VDD3: CN1.18 SB3.2 | length 12.4
  Top Layer w0.5: v1@17.55,24.25 SB3.2@18.544,24.25
  Internal 2 w0.5: v1(8.325,23.625) 14.325,23.625 14.95,24.25 v1(17.5,24.25)
  Bottom Layer w0.5: CN1.18@6.401,23.628 8.322,23.628 v1(8.325,23.625)
VDD4: C10.2 C13.2 CN1.30 CN3.3 JP1.1 U1.32 | length 62.4
  Top Layer w0.3: U1.32@22,29.825 22.475,29.825 22.8,29.5 C10.2@22.8,28.775
  Top Layer w0.5: CN3.3@19.561,2.544 19.607,2.59 19.607,3.857 v1(20.25,4.5) ; v1(22.8,26.925) C13.2@22.8,27.75 ; C13.2@22.8,27.775 C10.2@22.8,28.75
  Internal 2 w0.5: v1(8.55,16.025) 9.35,16.025 9.925,15.45 9.925,13.75 10.35,13.325 13.15,13.325 16.3,10.175 21.75,10.175 ; v1@20.25,4.482 21.762,5.994 21.762,10.206 22.8,11.244 v1(22.8,26.925) 25.625,26.925 26.7,28 26.7,33.3 28.425,35.025 JP1.1@30.75,35.025
  Bottom Layer w0.5: CN1.30@6.401,16.008 8.533,16.008 v1(8.55,16.025)
VDD5: C11.2 C14.2 CN1.32 U1.24 | length 27.6
  Top Layer w0.3: C11.2@15.55,28.75 15.55,29.433 15.967,29.85 16.95,29.85 17.6,30.5 U1.24@17.825,30.5
  Top Layer w0.5: v1(15.55,27.025) C14.2@15.55,27.75 C11.2@15.55,28.725
  Internal 2 w0.5: v1(8.55,15.25) 7.8,15.25 7,16.05 7,24.925 7.875,25.8 9.2,25.8 10.425,27.025 v1(15.55,27.025)
  Bottom Layer w0.5: CN1.32@6.401,14.738 6.496,14.833 8.133,14.833 v1(8.55,15.25)
pads on no net: CN1.3 CN1.4 CN1.5 CN1.10 CN1.16 CN1.19 CN1.20 CN1.21 CN1.23 CN1.27 CN1.39 CN1.41 CN1.43 CN1.48 CN1.50 CN2.1 CN2.3 CN2.4 CN2.5 CN2.6 CN2.12 CN2.16 CN2.17 CN2.18 CN2.19 CN2.24 CN2.28 CN2.30 CN2.31 CN2.33 CN2.36 CN2.47 CN2.49 CN3.1 CN3.2 CN3.8 CN3.9 CN3.10 CN3.NPTH1 CN3.NPTH2 Designator3.1 MIRE1.1 MIRE2.1 MIRE3.1 MIRE4.1 MIRE5.1 MIRE6.1

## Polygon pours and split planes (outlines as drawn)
GND on Top Layer "Top Layer-GND" (solid, remove dead copper, pour order 9): -6.693,46.75 44.006,46.75 44.006,-1.076 -6.693,-1.076
no net on Top Layer "RF_OUT" (solid, pour order 5): 18.086,34.103 18.004,33.83 17.707,33.82 17.641,34.077
GND on Internal 2 "Internal 2-GND" (solid, remove dead copper, pour order 11): -4.508,46.634 47.486,46.634 47.486,-0.721 -4.508,-0.721
GND on Internal 1 "Internal 1-GND" (solid, remove dead copper, pour order 13): 16.05,44.95 16.25,44.75 16.25,42.45 18.5,42.45 18.85,42.8 18.85,46.584 -2.679,46.584 -2.679,-1.635 44.793,-1.635 44.793,46.584 20.15,46.584 20.15,37.15 18.85,37.15 18.85,41.3 14.55,41.3 14.3,41.55 14.3,44.85 14.4,44.95
GND on Bottom Layer "Bottom Layer-GND" (solid, remove dead copper, pour order 7): -3.848,46.634 43.676,46.634 43.676,-1.508 -3.848,-1.508

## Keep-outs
Keep-Out Layer:
  lines w0.1: 43,1.141 43,45.795 41.78,47.015 30.285,47.015 29.45,47.85 29.45,53.6 28.8,54.25 24.415,54.25 18.625,54.25 14.15,54.25 13.55,53.65 13.55,47.85 12.715,47.015 1.26,47.015 0,45.755 0,1.139 1.139,0 41.852,0 42.504,0.647 43.001,1.141

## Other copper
Top Layer:
  pour cut-out: 13.95,34.75 13.95,36.25 15.15,36.25 15.15,35.25 15.9,35.25 15.9,33.75 14.85,33.75 14.85,34.75 14.025,34.75
  pour cut-out: 13.725,32.15 13.725,31.8 13.8,31.8 13.825,31.825 13.825,32.15
  pour cut-out: 14.3,44.85 14.4,44.95 16.05,44.95 16.25,44.75 16.25,42.35 14.3,42.35
  pour cut-out: 17.5,29.5 17.5,26.725 15,26.725 15,29.026 15.474,29.5
  pour cut-out: 18.65,26.275 19.325,26.275 19.325,26.125 18.65,26.125
  pour cut-out: 18.75,30.2 18.75,30.4 19.275,30.4 19.275,30.2
  text "1" at 2.25,41 h2 r90
Internal 1:
  text "2" at 2.25,42.25 h2 r90
Internal 2:
  text "3" at 2.25,44.5 h2 r90
Bottom Layer:
  text "4" at 2.25,46 h2 r90
Multi-Layer:
  pour cut-out: 0.5,40.5 2.75,40.5 2.75,46.6 0.5,46.6

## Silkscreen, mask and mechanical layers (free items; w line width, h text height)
Top Overlay:
  lines w0.05: -0.592,0 1.139,0 ; 0,-0.5 0,1.139
  text "L" at 3,39.7 h13
  text "BOOT" at 32.75,35.267 h1.5
  text "Loader" at 32.75,34.015 h1.5
  text "USER" at 32.5,30.017 h1.5
  text "FLASH" at 32.5,28.767 h1.5
  text "J" at 2.75,6 h8
  text "K" at 34,3.6 h13
  text "MB2032B" at 2.25,2.75 h2.5
Bottom Overlay:
  text "H" at 41,42.75 h7.62
  text "E" at 28,41.5 h7.62
  text "F" at 21.75,41.25 h7.62
  text "C" at 34.75,41.25 h7.62
  text "G" at 9.25,41 h7.62
  text "S" at 15.5,41 h6
  text "I" at 40.5,38.5 h7.62
Top Solder:
  region: 2.5,40.75 2.5,46.35 0.75,46.35 0.75,40.75
Bottom Solder:
  region: 2.5,40.75 2.5,46.35 0.75,46.35 0.75,40.75
M1-Board Shape:
  lines w0.1: 1.245,47 0,45.755 0,45.75 0,1.139 1.139,0 41.852,0 43.001,1.141 ; 1.26,47.015 1.282,47.037 12.742,47.037 13.563,47.858 13.563,53.615 14.198,54.25 28.803,54.25 29.438,53.615 29.438,47.855 30.257,47.035 ; 30.257,47.015 41.78,47.015 43,45.795 ; 43,1.141 43,45.795 ; 43.001,45.795 43,45.795
M2-Board Dimensions:
  lines w0.1: -5.613,47 0.61,47 ; -5.334,0 0.889,0 ; 0,-11.198 0,0.464 ; 43,-10.994 43,0.667
  lines w0.254: -5.798,2 -5.131,0 ; -5.797,45 -5.131,47 ; -5.385,0 -4.877,0 ; -5.385,47 -4.877,47 ; -5.131,19.955 -5.131,0 ; -5.131,27.045 -5.131,47 ; -4.464,2 -5.131,0 ; -4.464,45 -5.131,47 ; 0,-11.121 0,-10.613 ; 2,-11.534 0,-10.867 ; 2,-10.201 0,-10.867 ; 17.955,-10.867 0,-10.867 ; 25.045,-10.867 43,-10.867 ; 41,-11.534 43,-10.867 ; 41,-10.201 43,-10.867 ; 43,-11.121 43,-10.613
  text "47 (mm)" at -4.29,20.209 h2 r90
  text "43 (mm)" at 18.209,-11.708 h2
M4-Bottom Dimensions:
  lines w0.1: -1.323,33.788 2.334,33.788 ; 2.334,-5 2.334,33.788 ; 36.624,-5 36.624,33.788 ; 44.448,33.788 2.334,33.788
  lines w0.254: 2.334,-5.254 2.334,-4.746 ; 4.334,-5.667 2.334,-5 ; 4.334,-4.333 2.334,-5 ; 14.717,-5 2.334,-5 ; 24.242,-5 36.624,-5 ; 34.624,-5.667 36.624,-5 ; 34.624,-4.333 36.624,-5 ; 36.624,-5.254 36.624,-4.746
  text "34.29 (mm)" at 14.971,-5.841 h2
  text "CN1/CN2 spacing" at 12.954,-7.595 h2
Drill Drawing:
  drawing of 231 lines, arcs and shapes, not listed
  text "mils" at 31.397,176.353 h2.54
  text "mils" at 19.916,176.302 h2.54
  text "+/-10%" at 75.487,169.18 h3
  text "50 ohm" at 44.987,169.142 h3
  text "TOP" at -3.325,169.108 h3
  text "5.905" at 18.237,169.108 h3
  text "5.708" at 30.81,169.108 h3
  text "NA" at 61.487,169.108 h3
  text "Layer" at -0.942,115.974 h1.55
  text "Name" at 5.548,115.974 h1.55
  text "Material" at 18.101,115.974 h1.55
  text "Thickness" at 29.381,115.974 h1.55
  text "Constant" at 38.646,115.974 h1.55
  text "Board Layer Stack" at 47.221,115.974 h1.55
  text "Top Overlay" at 5.548,112.874 h1.55
  text "Top Solder" at 5.548,109.774 h1.55
  text "Solder Resist" at 18.101,109.774 h1.55
  text "0,015mm" at 29.381,109.774 h1.55
  text "3.5" at 38.646,109.774 h1.55
  text "1" at -0.942,106.674 h1.55
  text "Top Layer" at 5.548,106.674 h1.55
  text "0,042mm" at 29.381,106.674 h1.55
  text "Dielectric 1" at 5.548,103.574 h1.55
  text "FR-4" at 18.101,103.574 h1.55
  text "0,106mm" at 29.381,103.574 h1.55
  text "4.2" at 38.646,103.574 h1.55
  text "2" at -0.943,100.474 h1.55
  text "Internal 1" at 5.548,100.474 h1.55
  text "0,035mm" at 29.381,100.474 h1.55
  text "Dielectric 3" at 5.548,97.374 h1.55
  text "1,248mm" at 29.381,97.374 h1.55
  text "4.2" at 38.646,97.374 h1.55
  text "3" at -0.942,94.274 h1.55
  text "Internal 2" at 5.548,94.274 h1.55
  text "0,035mm" at 29.381,94.274 h1.55
  text "Dielectric 2" at 5.548,91.174 h1.55
  text "0,106mm" at 29.381,91.174 h1.55
  text "4.2" at 38.646,91.174 h1.55
  text "4" at -0.942,88.074 h1.55
  text "Bottom Layer" at 5.548,88.074 h1.55
  text "0,042mm" at 29.381,88.074 h1.55
  text "Bottom Solder" at 5.548,84.974 h1.55
  text "Solder Resist" at 18.101,84.974 h1.55
  text "0,015mm" at 29.381,84.974 h1.55
  text "3.5" at 38.646,84.974 h1.55
  text "Bottom Overlay" at 5.548,81.874 h1.55
  text "Symbol" at -0.019,76.617 h2.16
  text "Count" at 8.443,76.617 h2.16
  text "Hole Size" at 17.221,76.617 h2.16
  text "Plated" at 32.772,76.617 h2.16
  text "Hole Type" at 40.2,76.617 h2.16
  text "Drill Layer Pair" at 51.014,76.617 h2.16
  text "Via/Pad" at 71.513,76.617 h2.16
  text "Pad Shape" at 80.375,76.617 h2.16
  text "Template" at 91.951,76.617 h2.16
  text "Description" at 106.373,76.617 h2.16
  text "17" at 8.443,72.889 h1.8
  text "0,20mm (7,87mil)" at 17.221,72.889 h1.8
  text "PTH" at 32.772,72.889 h1.8
  text "Round" at 40.2,72.889 h1.8
  text "Top Layer - Bottom Layer" at 51.014,72.889 h1.8
  text "Via" at 71.513,72.889 h1.8
  text "Rounded" at 80.375,72.889 h1.8
  text "v45h20m0mx0" at 91.951,72.889 h1.8
  text "564" at 8.443,69.161 h1.8
  text "0,30mm (11,81mil)" at 17.221,69.161 h1.8
  text "PTH" at 32.772,69.161 h1.8
  text "Round" at 40.2,69.161 h1.8
  text "Top Layer - Bottom Layer" at 51.014,69.161 h1.8
  text "Via" at 71.513,69.161 h1.8
  text "Rounded" at 80.375,69.161 h1.8
  text "v60h30m0mx0" at 91.951,69.161 h1.8
  text "2" at 8.443,65.433 h1.8
  text "1,00mm (39,37mil)" at 17.221,65.433 h1.8
  text "NPTH" at 32.772,65.433 h1.8
  text "Round" at 40.2,65.433 h1.8
  text "Top Layer - Bottom Layer" at 51.014,65.433 h1.8
  text "Pad" at 71.513,65.433 h1.8
  text "Rounded" at 80.375,65.433 h1.8
  text "c0hn100m105p-1" at 91.951,65.433 h1.8
  text "3" at 8.443,61.704 h1.8
  text "1,00mm (39,37mil)" at 17.221,61.704 h1.8
  text "PTH" at 32.772,61.704 h1.8
  text "Round" at 40.2,61.704 h1.8
  text "Top Layer - Bottom Layer" at 51.014,61.704 h1.8
  text "Pad" at 71.513,61.704 h1.8
  text "Rounded" at 80.375,61.704 h1.8
  text "(Mixed)" at 91.951,61.704 h1.8
  text "586 Total" at 8.443,57.976 h1.8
